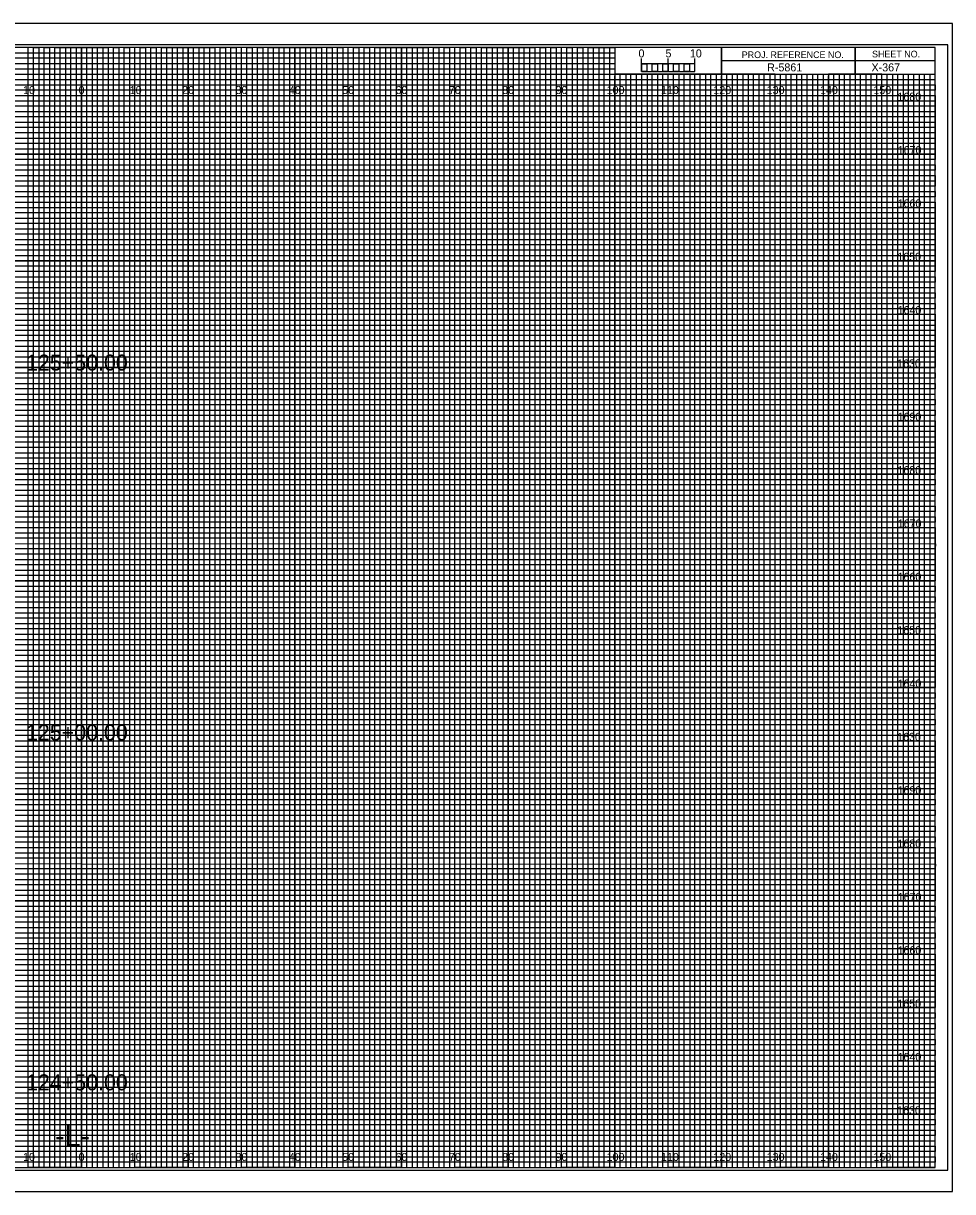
# Model space of a CAD drawing. Extents: x -13 to 323, y -5 to 2414.
# Drawn here: x 149.1 to 323.3, y 655.5 to 874.5 of the extents above; entities that cross this region are included whole.
import ezdxf

# ---------------------------------------------------------------- set-up
doc = ezdxf.new("R2010")
doc.units = 0
for name, color, linetype in [('Prop XS Alignment Label', 7, 'Continuous'), ('Prop XS Bar Scale Labels', 7, 'Continuous'), ('Prop XS Elevation Labels', 7, 'Continuous'), ('Prop XS Offset Labels', 7, 'Continuous'), ('Prop XS Project Number', 7, 'Continuous'), ('Prop XS Sheet Number', 7, 'Continuous'), ('Prop XS Station Labels', 7, 'Continuous'), ('Sheet Cross Section CELL', 7, 'Continuous'), ('Sheet Cross Section Grid Major CELL', 7, 'Continuous'), ('Sheet Cross Section Grid Middle CELL', 7, 'Continuous'), ('Sheet Cross Section Grid Minor 1 CELL', 7, 'Continuous'), ('Sheet Cross Section Grid Minor 2 CELL', 7, 'Continuous'), ('Sheet Cross Section Scale CELL', 7, 'Continuous'), ('Sheet Cutting Line CELL', 7, 'Continuous'), ('Sheet DOT Grid CELL', 7, 'Continuous'), ('Sheet Plot Border Inside CELL', 7, 'Continuous'), ('Sheet Plot Border Outside CELL', 7, 'Continuous')]:
    doc.layers.add(name, color=color, linetype=linetype)

msp = doc.modelspace()

# ---------------------------------------------------------------- linework, layer by layer
at = {"layer": 'Sheet Cross Section CELL'}
for p, q in [((305, 870), (305, 865)), ((305, 865), (305, 870)), ((280, 867.5), (280, 865)), ((320, 867.49), (280, 867.49)), ((280, 865), (320, 865))]:
    msp.add_line(p, q, dxfattribs=at)
for points in [[(320, 870), (0, 870), (0, 660), (320, 660)], [(280, 870), (260, 870), (260, 865.03), (280, 865.03)], [(320, 870), (280, 870), (280, 865), (320, 865)]]:
    msp.add_lwpolyline(points, close=True, dxfattribs=at)
at = {"layer": 'Sheet Cross Section Grid Major CELL'}
for p, q in [((150, 870), (140, 870)), ((150, 660), (150, 870)), ((170, 870), (160, 870)), ((160, 870), (160, 660)), ((170, 660), (170, 870)), ((190, 870), (180, 870)), ((180, 870), (180, 660)), ((190, 660), (190, 870)), ((210, 870), (200, 870)), ((200, 870), (200, 660)), ((210, 660), (210, 870)), ((230, 870), (220, 870)), ((220, 870), (220, 660)), ((230, 660), (230, 870)), ((250, 870), (240, 870)), ((240, 870), (240, 660)), ((250, 660), (250, 870)), ((260, 870), (260, 660)), ((270, 660), (270, 865)), ((290, 865), (280, 865)), ((280, 865), (280, 660)), ((290, 660), (290, 865)), ((310, 865), (300, 865)), ((300, 865), (300, 660)), ((310, 660), (310, 865)), ((160, 660), (150, 660)), ((180, 660), (170, 660)), ((200, 660), (190, 660)), ((220, 660), (210, 660)), ((240, 660), (230, 660)), ((260, 660), (250, 660)), ((280, 660), (270, 660)), ((300, 660), (290, 660)), ((320, 660), (310, 660)), ((320, 660), (320, 660))]:
    msp.add_line(p, q, dxfattribs=at)
for points in [[(0, 860), (320, 860), (320, 850), (0, 850)], [(0, 840), (320, 840), (320, 830), (0, 830)], [(0, 820), (320, 820), (320, 810), (0, 810)], [(0, 800), (320, 800), (320, 790), (0, 790)], [(0, 780), (320, 780), (320, 770), (0, 770)], [(0, 760), (320, 760), (320, 750), (0, 750)], [(0, 740), (320, 740), (320, 730), (0, 730)], [(0, 720), (320, 720), (320, 710), (0, 710)], [(0, 700), (320, 700), (320, 690), (0, 690)], [(0, 680), (320, 680), (320, 670), (0, 670)]]:
    msp.add_lwpolyline(points, dxfattribs=at)
at = {"layer": 'Sheet Cross Section Grid Middle CELL'}
for points in [[(145, 660), (155, 660), (155, 870), (165, 870), (165, 660), (175, 660), (175, 870), (185, 870), (185, 660), (195, 660), (195, 870), (205, 870), (205, 660), (215, 660), (215, 870), (225, 870), (225, 660), (235, 660), (235, 870), (245, 870), (245, 660), (255, 660), (255, 870), (259.93, 870), (260, 870), (260, 865), (264.99, 865), (264.99, 660), (275, 660), (275, 865), (285, 865), (285, 660), (295, 660), (295, 865), (305, 865), (305, 660), (315, 660), (315, 865)], [(0, 865), (275, 865)], [(0, 845), (320, 845), (320, 855), (0, 855)], [(0, 825), (320, 825), (320, 835), (0, 835)], [(0, 805), (320, 805), (320, 815), (0, 815)], [(0, 785), (320, 785), (320, 795), (0, 795)], [(0, 765), (320, 765), (320, 775), (0, 775)], [(0, 745), (320, 745), (320, 755), (0, 755)], [(0, 725), (320, 725), (320, 735), (0, 735)], [(0, 705), (320, 705), (320, 715), (0, 715)], [(0, 685), (320, 685), (320, 695), (0, 695)], [(0, 665), (320, 665), (320, 675), (0, 675)]]:
    msp.add_lwpolyline(points, dxfattribs=at)
at = {"layer": 'Sheet Cross Section Grid Minor 1 CELL'}
for p, q in [((0, 869), (260, 869)), ((260, 867.98), (0, 867.98)), ((260, 869), (260, 867.98)), ((0, 867), (260, 867)), ((260, 865.89), (0, 865.89)), ((260, 867), (260, 865.89)), ((0, 864), (320, 864))]:
    msp.add_line(p, q, dxfattribs=at)
for points in [[(0, 863), (270, 863), (320, 863), (320, 862), (0, 862)], [(0, 861), (320, 861), (320, 859), (0, 859)], [(0, 858), (320, 858), (320, 857), (0, 856.98)], [(0, 856), (320, 856), (320, 854), (0, 854)], [(0, 853), (320, 853), (320, 852), (0, 852)], [(0, 851), (320, 851), (320, 849), (0, 849)], [(0, 848), (320, 848), (320, 847), (0, 847)], [(0, 846), (320, 846), (320, 844), (0, 844)], [(0, 843), (320, 843), (320, 842), (0, 842)], [(0, 841), (320, 841), (320, 839), (0, 839)], [(0, 838), (320, 838), (320, 837), (0, 837)], [(0, 836), (320, 836), (320, 833.95), (320, 833), (320, 832), (0, 832)], [(0, 834), (320, 834), (320, 833), (0, 833)], [(0, 831), (320, 831), (320, 829), (0, 829.03)], [(0, 829.03), (320, 829), (320, 828), (0, 828)], [(0, 827), (320, 827), (320, 826), (0, 826)], [(0, 824), (320, 824), (320, 823), (0, 823)], [(0, 822), (320, 822), (320, 821), (0, 821)], [(-0.07, 818.89), (320, 818.89), (320, 817.88), (-0.07, 817.88)], [(0, 817), (320, 817), (320, 816), (0, 816)], [(0, 814), (320, 814), (320, 813), (0, 813)], [(0, 812), (320, 812), (320, 811), (0, 811)], [(0, 809), (320, 809), (320, 808), (0, 808)], [(0, 807), (320, 807), (320, 806), (0, 806)], [(0, 804), (320, 804), (320, 803), (0, 803)], [(0, 802), (320, 802), (320, 801), (0, 801)], [(0, 799), (320, 799), (319.99, 797.98), (0, 798)], [(0, 797), (320, 797), (320, 796), (0, 796)], [(0, 794), (320, 794), (320, 793), (0, 793)], [(0, 792), (320, 792), (320, 791), (0, 791)], [(0, 789), (320, 789), (320, 788), (0, 788)], [(0, 787), (320, 787), (320, 786), (0, 786)], [(0, 784), (320, 784), (320, 783), (0, 783)], [(0, 782), (320, 782), (320, 781), (0, 781)], [(0, 779), (320, 779), (320, 778), (0, 778)], [(0, 776.99), (320.07, 776.91), (320, 776), (0, 776)], [(0, 774), (320, 774), (320, 773), (0, 773)], [(0, 772), (320, 772), (320, 771), (0, 771)], [(0, 769), (320, 769), (320, 768), (0, 768)], [(0, 767), (320, 767), (320, 766), (0, 766)], [(0, 764), (320, 764), (320, 763), (0, 763)], [(0, 762), (320, 762), (320, 761), (0, 761)], [(0, 759), (320, 759), (320, 758), (0, 758)], [(0, 757), (320, 757), (320, 756), (0, 756)], [(0, 754), (320, 754), (320, 753), (0, 753)], [(0, 752), (320, 752), (320, 751), (0, 751)], [(0, 749), (320, 749), (320, 748), (0, 748)], [(0, 747), (320, 747), (320, 746), (0, 746)], [(0, 744), (320, 744), (320, 743), (0, 743)], [(0, 742), (320, 742), (320, 741), (0, 741)], [(0, 739), (320, 739), (319.99, 737.98), (0, 738)], [(0, 737), (320, 737), (320, 736), (0, 736)], [(0, 734), (320, 734), (320, 733), (0, 733)], [(0, 732), (320, 732), (320, 731), (0, 731)], [(0, 729), (320, 729), (320, 728), (0, 728)], [(0, 727), (320, 727), (320, 726), (0, 726)], [(0, 724), (320, 724), (320, 723), (0, 723)], [(0, 722), (320, 722), (320, 721), (0, 721)], [(0, 719), (320, 719), (320, 718), (0, 718)], [(0, 716.99), (320.07, 716.91), (320, 716), (0, 716)], [(0, 714), (320, 714), (320, 713), (0, 713)], [(0, 712), (320, 712), (320, 711), (0, 711)], [(0, 709), (320, 709), (320, 708), (0, 708)], [(0, 707), (320, 707), (320, 706), (0, 706)], [(0, 704), (320, 704), (320, 703), (0, 703)], [(0, 702), (320, 702), (320, 701), (0, 701)], [(0, 699), (320, 699), (320, 698), (0, 698)], [(0, 697), (320, 697), (320, 696), (0, 696)], [(0, 694), (320, 694), (320, 693), (0, 693)], [(0, 692), (320, 692), (320, 691), (0, 691)], [(0, 689), (320, 689), (320, 688), (0, 688)], [(0, 687), (320, 687), (320, 686), (0, 686)], [(0, 684), (320, 684), (320, 683), (0, 683)], [(0, 682), (320, 682), (320, 681), (0, 681)], [(0, 679), (320, 679), (320, 678), (0, 678)], [(0, 677), (320, 677), (320, 676), (0, 676)], [(0, 674), (320, 674), (320, 673), (0, 673)], [(0, 672), (320, 672), (320, 671), (0, 671)], [(0, 669), (320, 669), (320, 668), (0, 668)], [(0, 667), (320, 667), (320, 666), (0, 666)], [(0, 664), (320, 664), (320, 663), (0, 663)], [(0, 662), (320, 662), (320, 661), (0, 661)]]:
    msp.add_lwpolyline(points, dxfattribs=at)
at = {"layer": 'Sheet Cross Section Grid Minor 2 CELL'}
for p, q in [((267, 865), (266.01, 865)), ((266.01, 865), (266.01, 660)), ((267, 660), (267, 865)), ((269, 865), (268, 865)), ((268, 865), (268, 660)), ((269, 660), (269, 865)), ((266.01, 660), (265, 660)), ((268, 660), (267, 660))]:
    msp.add_line(p, q, dxfattribs=at)
for points in [[(150, 660), (151, 660), (151, 870), (152, 870), (152, 660)], [(152, 660), (153, 660), (153, 870), (154, 870), (154, 660)], [(155, 660), (156, 660), (156, 870), (157, 870), (157, 660)], [(157, 660), (158, 660), (158, 870), (159, 870), (159, 660)], [(160, 660), (161, 660), (161, 870), (162, 870), (162, 660)], [(162, 660), (163, 660), (163, 870), (164, 870), (164, 660)], [(165, 660), (166, 660), (166, 870), (167, 870), (167, 660)], [(167, 660), (168, 660), (168, 870), (169, 870), (169, 660)], [(170, 660), (171, 660), (171, 870), (172, 870), (172, 660)], [(172, 660), (173, 660), (173, 870), (174, 870), (174, 660)], [(175, 660), (176, 660), (176, 870), (177, 870), (177, 660)], [(177, 660), (178, 660), (178, 870), (179, 870), (179, 660)], [(180, 660), (181, 660), (181, 870), (182, 870), (182, 660)], [(182, 660), (183, 660), (183, 870), (184, 870), (184, 660)], [(185, 660), (186, 660), (186, 870), (187, 870), (187, 660)], [(187, 660), (188, 660), (188, 870), (189, 870), (189, 660)], [(190, 660), (191, 660), (191, 870), (192, 870), (192, 660)], [(192, 660), (193, 660), (193, 870), (194, 870), (194, 660)], [(195, 660), (196, 660), (196, 870), (197, 870), (197, 660)], [(197, 660), (198, 660), (198, 870), (199, 870), (199, 660)], [(200, 660), (201, 660), (201, 870), (202, 870), (202, 660)], [(202, 660), (203, 660), (203, 870), (204, 870), (204, 660)], [(205, 660), (206, 660), (206, 870), (207, 870), (207, 660)], [(207, 660), (208, 660), (208, 870), (209, 870), (209, 660)], [(210, 660), (211, 660), (211, 870), (212, 870), (212, 660)], [(212, 660), (213, 660), (213, 870), (214, 870), (214, 660)], [(215, 660), (216, 660), (216, 870), (217, 870), (217, 660)], [(217, 660), (218, 660), (218, 870), (219, 870), (219, 660)], [(220, 660), (221, 660), (221, 870), (222, 870), (222, 660)], [(222, 660), (223, 660), (223, 870), (224, 870), (224, 660)], [(225, 660), (226, 660), (226, 870), (227, 870), (227, 660)], [(227, 660), (228, 660), (228, 870), (229, 870), (229, 660)], [(230, 660), (231, 660), (231, 870), (232, 870), (232, 660)], [(232, 660), (233, 660), (233, 870), (234, 870), (234, 660)], [(235, 660), (236, 660), (236, 870), (237, 870), (237, 660)], [(237, 660), (238, 660), (238, 870), (239, 870), (239, 660)], [(240, 660), (241, 660), (241, 870), (242, 870), (242, 660)], [(242, 660), (243, 660), (243, 870), (244, 870), (244, 660)], [(245, 660), (246, 660), (246, 870), (247, 870), (247, 660)], [(247, 660), (248, 660), (248, 870), (249, 870), (249, 660)], [(250, 660), (251, 660), (251, 870), (252, 870), (252, 660)], [(252, 660), (253, 660), (253, 870), (254, 870), (254, 660)], [(255, 660), (256, 660), (256, 870), (257, 870), (257, 660)], [(257, 660), (258, 660), (258, 870), (259, 870), (259, 660)], [(260, 660), (261, 660), (261, 865), (262.02, 865), (262.02, 660)], [(262, 660), (263, 660), (263, 865), (263.99, 865), (263.99, 660)], [(270, 660), (270.98, 660), (270.98, 865), (272, 865), (272, 660)], [(272, 660), (273, 660), (273, 865), (274.05, 865), (274.05, 660)], [(275, 660), (276, 660), (276, 865), (277, 865), (277, 660)], [(277, 660), (278, 660), (278, 865), (279, 865), (279, 660)], [(280, 660), (281, 660), (281, 865), (282, 865), (282, 660)], [(282, 660), (283, 660), (283, 865), (284, 865), (284, 660)], [(285, 660), (286, 660), (286, 865), (287, 865), (287, 660)], [(287, 660), (288, 660), (288, 865), (289, 865), (289, 660)], [(290, 660), (291, 660), (291, 865), (292, 865), (292, 660)], [(292, 660), (293, 660), (293, 865), (294, 865), (294, 660)], [(295, 660), (296, 660), (296, 865), (297, 865), (297, 660)], [(297, 660), (298, 660), (298, 865), (299, 865), (299, 660)], [(300, 660), (301, 660), (301, 865), (302, 865), (302, 660)], [(302, 660), (303, 660), (303, 865), (304, 865), (304, 660)], [(305, 660), (306, 660), (306, 865), (307, 865), (307, 660)], [(307, 660), (308, 660), (308, 865), (309, 865), (309, 660)], [(310, 660), (311, 660), (311, 865), (312, 865), (312, 660)], [(312, 660), (313, 660), (313, 865), (314, 865), (314, 660)], [(315, 660), (316, 660), (316, 865), (317, 865), (317, 660)], [(317, 660), (318, 660), (318, 865), (319, 865), (319, 660)]]:
    msp.add_lwpolyline(points, dxfattribs=at)
at = {"layer": 'Sheet Cross Section Scale CELL'}
for p, q in [((265, 865.49), (265, 867.9)), ((265, 866.9), (265, 867.9)), ((270, 865.49), (270, 867.9)), ((275, 865.49), (275, 867.9)), ((275, 866.9), (275, 867.9))]:
    msp.add_line(p, q, dxfattribs=at)
for points in [[(275, 866.9), (265, 866.9), (265, 865.49), (275, 865.49)], [(265, 866.9), (266, 866.9), (266, 865.49), (265, 865.49)], [(267, 866.9), (268, 866.9), (268, 865.49), (267, 865.49)], [(269, 866.9), (270, 866.9), (270, 865.49), (269, 865.49)], [(271, 866.9), (272, 866.9), (272, 865.49), (271, 865.49)], [(273, 866.9), (274, 866.9), (274, 865.49), (273, 865.49)]]:
    msp.add_lwpolyline(points, close=True, dxfattribs=at)
at = {"layer": 'Sheet Cutting Line CELL'}
for p, q in [((323.3, 874.5), (-13.4, 874.5)), ((-13.4, 655.5), (323.3, 655.5))]:
    msp.add_line(p, q, dxfattribs=at)
at = {"layer": 'Sheet DOT Grid CELL'}
for p, q in [((150, 660), (150, 870)), ((160, 660), (160, 870)), ((170, 660), (170, 870)), ((180, 660), (180, 870)), ((190, 660), (190, 870)), ((200, 660), (200, 870)), ((210, 660), (210, 870)), ((220, 660), (220, 870)), ((230, 660), (230, 870)), ((240, 660), (240, 870)), ((250, 660), (250, 870)), ((260, 660), (260, 864.69)), ((270, 660), (270, 864.69)), ((280, 660), (280, 864.69)), ((290, 660), (290, 864.69)), ((300, 660), (300, 864.69)), ((310, 660), (310, 864.69)), ((0, 860), (320, 860)), ((0, 850), (320, 850)), ((0, 840), (320, 840)), ((0, 830), (320, 830)), ((0, 820), (320, 820)), ((0, 810), (320, 810)), ((0, 800), (320, 800)), ((0, 790), (320, 790)), ((0, 780), (320, 780)), ((0, 770), (320, 770)), ((0, 760), (320, 760)), ((0, 750), (320, 750)), ((0, 740), (320, 740)), ((0, 730), (320, 730)), ((0, 720), (320, 720)), ((0, 710), (320, 710)), ((0, 700), (320, 700)), ((0, 690), (320, 690)), ((0, 680), (320, 680)), ((0, 670), (320, 670))]:
    msp.add_line(p, q, dxfattribs=at)
at = {"layer": 'Sheet Plot Border Inside CELL'}
msp.add_lwpolyline([(-10.8, 659.5), (322.4, 659.5), (322.4, 870.5), (-10.8, 870.5)], close=True, dxfattribs=at)
at = {"layer": 'Sheet Plot Border Outside CELL'}
msp.add_lwpolyline([(-13.4, 655.5), (323.3, 655.5), (323.3, 874.5), (-13.4, 874.5)], close=True, dxfattribs=at)

# ---------------------------------------------------------------- texts
at = {"layer": 'Prop XS Alignment Label'}
msp.add_text('-L-', height=4, dxfattribs=at).set_placement((155.06, 664))
at = {"layer": 'Prop XS Bar Scale Labels'}
for s, p in [('5', (269.47, 868.12)), ('10', (274.04, 868.12))]:
    msp.add_text(s, height=1.5, dxfattribs=at).set_placement(p)
at = {"layer": 'Prop XS Elevation Labels'}
for s, p in [('1680', (312.95, 860)), ('1670', (313, 850)), ('1660', (312.97, 840)), ('1650', (312.92, 830)), ('1640', (312.97, 820)), ('1630', (312.89, 810)), ('1690', (312.97, 800)), ('1680', (312.95, 790)), ('1670', (313, 780)), ('1660', (312.97, 770)), ('1650', (312.92, 760)), ('1640', (312.97, 750)), ('1630', (312.89, 740)), ('1690', (312.97, 730)), ('1680', (312.95, 720)), ('1670', (313, 710)), ('1660', (312.97, 700)), ('1650', (312.92, 690)), ('1640', (312.97, 680)), ('1630', (312.89, 670))]:
    msp.add_text(s, height=1.5, dxfattribs=at).set_placement(p)
at = {"layer": 'Prop XS Offset Labels'}
for s, p in [('10', (149.04, 861.25)), ('0', (159.45, 861.25)), ('0', (159.45, 861.25)), ('10', (169.04, 861.25)), ('20', (178.86, 861.25)), ('30', (188.86, 861.25)), ('40', (198.86, 861.25)), ('50', (208.86, 861.25)), ('60', (218.86, 861.25)), ('70', (228.86, 861.25)), ('80', (238.86, 861.25)), ('90', (248.86, 861.25)), ('100', (258.44, 861.25)), ('110', (268.62, 861.25)), ('120', (278.44, 861.25)), ('130', (288.44, 861.25)), ('140', (298.44, 861.25)), ('150', (308.44, 861.25)), ('10', (149.04, 661.25)), ('0', (159.45, 661.25)), ('0', (159.45, 661.25)), ('10', (169.04, 661.25)), ('20', (178.86, 661.25)), ('30', (188.86, 661.25)), ('40', (198.86, 661.25)), ('50', (208.86, 661.25)), ('60', (218.86, 661.25)), ('70', (228.86, 661.25)), ('80', (238.86, 661.25)), ('90', (248.86, 661.25)), ('100', (258.44, 661.25)), ('110', (268.62, 661.25)), ('120', (278.44, 661.25)), ('130', (288.44, 661.25)), ('140', (298.44, 661.25)), ('150', (308.44, 661.25))]:
    msp.add_text(s, height=1.5, dxfattribs=at).set_placement(p)
at = {"layer": 'Prop XS Project Number'}
msp.add_text('R-5861', height=1.5, dxfattribs=at).set_placement((288.53, 865.5))
at = {"layer": 'Prop XS Sheet Number'}
msp.add_text('X-367', height=1.5, dxfattribs=at).set_placement((308.09, 865.5))
at = {"layer": 'Prop XS Station Labels'}
for s, p in [('125+50.00', (149.59, 809.41)), ('125+00.00', (149.59, 740.08)), ('124+50.00', (149.59, 674.49))]:
    msp.add_text(s, height=3, dxfattribs=at).set_placement(p)
at = {"layer": 'Sheet Cross Section CELL'}
for s, p in [('PROJ. REFERENCE NO.', (283.77, 867.99)), ('SHEET NO.', (308.19, 868.12))]:
    msp.add_text(s, height=1.25, dxfattribs=at).set_placement(p)
at = {"layer": 'Sheet Cross Section Scale CELL'}
msp.add_text('0', height=1.5, dxfattribs=at).set_placement((264.41, 868.12))

doc.saveas('drawing.dxf')
